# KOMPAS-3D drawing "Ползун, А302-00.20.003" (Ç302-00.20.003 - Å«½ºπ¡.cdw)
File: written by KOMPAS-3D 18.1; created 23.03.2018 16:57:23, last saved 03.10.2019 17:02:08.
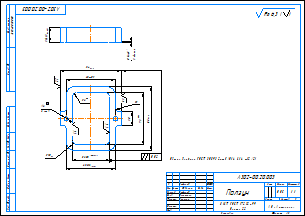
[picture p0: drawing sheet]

Sheet 1: A3, landscape

Document properties: Автор: Милов; Организация: Милов; Полное имя файла: D:\Мембранные насосы\Мембранный электропривод\А302-00.00.000 - ASTRA-302 (МЭ200)\Архив\А302-00.00.000 Чертежи\А302-00.20.003 - Ползун.cdw; Масса: 0.0527789

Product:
- Part/product: Ползун  | designation А302-00.20.003
    Материал: Полиамид П-12Б-20  ТУ 6-05-898-73 (density 1020 kg/m3)
    Масса: 0.0527789
    Раздел спецификации: Детали
    Форматы листов документа: A3

Title block, sheet 1: Наименование: Ползун; designation: А302-00.20.003; Материал: Д16Т ГОСТ 17232-99 / Плита 22; Масса: 0,05; scale: 1:1; Количество листов документа: 1; organisation: АО «Астерион»; Форматы листов документа: A3; stored path: \\192.168.87.28\Konstructor_doc\Мембранные насосы\Мембранный электропривод\А302-00.00.000 - ASTRA-302 (МЭ200)\Чертежи\А302-00.20.003 - Ползун.cdw; Разработал: Лифлянд; Проверил: Борисенко; Т. контр.: Лучихин

Views: Вид 1, Спереди, Проекционный вид 2
Referenced files in Z:\Мембранные насосы\Мембранный электропривод\А302-00.00.000 - ASTRA-302 (МЭ200)\3Д\: А302-00.20.003 - Ползун.m3d
Referenced files in D:\Мембранные насосы\Мембранный электропривод\А302-00.00.000 - ASTRA-302 (МЭ200)\3Д\: А302-00.20.003 - Ползун.m3d
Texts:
  Ra 6,3
  Ra 6,3 ( )
Dimensions and other numbers on the sheet: 0,5; 2 фаски; 21; 52; 68±0,1; 84; 20; 72; 88; 6; 10; 2 отв.; 0,02; 1,6; 3,2; 1; 3; 1:1; 0,05; 03.10.2019

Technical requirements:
  Общие допуски ГОСТ 30893.2-mK (H14, h14,  t2/2).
